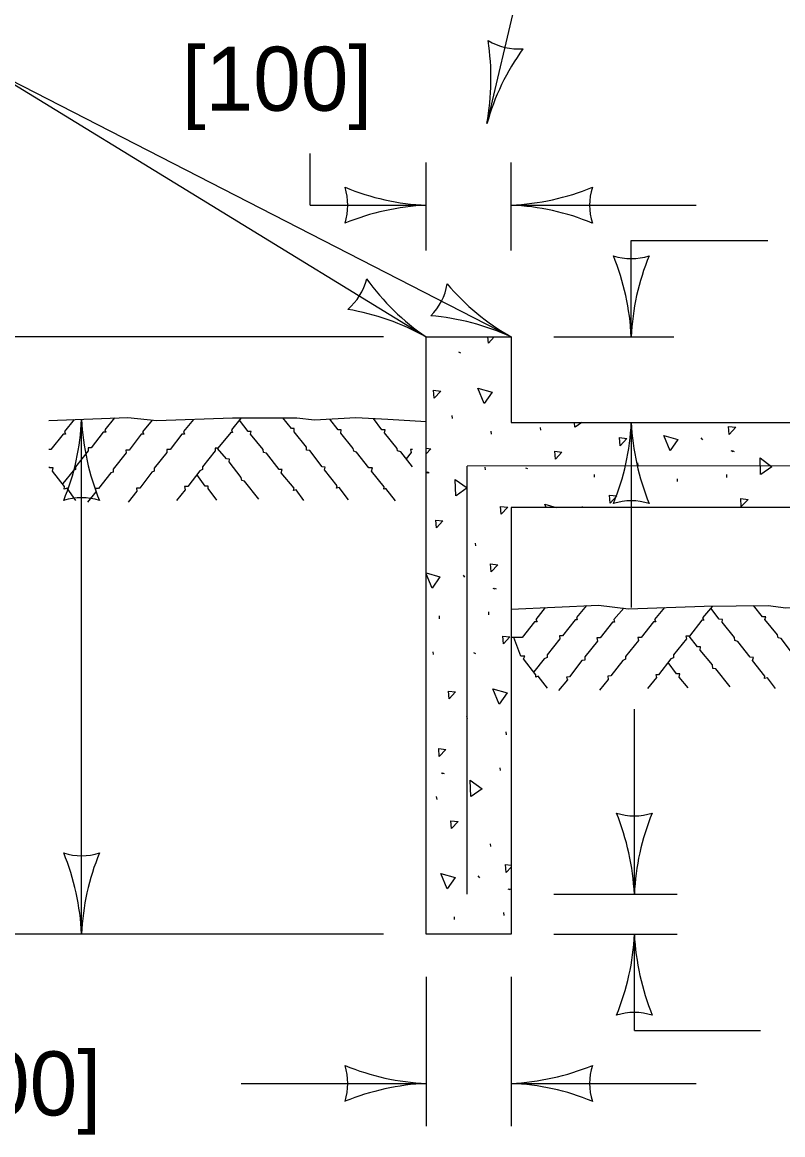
# Model space of a CAD drawing. Extents: x 49991.4 to 50021, y 49987.6 to 50011.4.
# Drawn here: x 50000.909 to 50001.622, y 49989.384 to 49990.427 of the extents above; entities that cross this region are included whole.
import ezdxf

# ---------------------------------------------------------------- set-up
doc = ezdxf.new("R2010")
doc.units = 0
for name, color, linetype in [('Level 1', 7, 'Continuous'), ('Level 2', 7, 'Continuous'), ('Level 3', 7, 'Continuous')]:
    doc.layers.add(name, color=color, linetype=linetype)

msp = doc.modelspace()

# ---------------------------------------------------------------- linework, layer by layer
at = {"layer": 'Level 1'}
for p, q in [((50001.2875, 49989.5723), (50001.2875, 49990.1317)), ((50001.2875, 49990.1317), (50001.3671, 49990.1317)), ((50001.3671, 49990.1317), (50001.3671, 49990.0516)), ((50001.3179, 49990.1177), (50001.3197, 49990.1169)), ((50001.3121, 49990.0554), (50001.3117, 49990.0581)), ((50001.3487, 49990.0406), (50001.3485, 49990.0433)), ((50001.3671, 49990.0516), (50002.1666, 49990.0516)), ((50001.395, 49990.0444), (50001.3947, 49990.047)), ((50001.5449, 49990.0371), (50001.5463, 49990.0352)), ((50001.5729, 49990.0252), (50001.5748, 49990.0243)), ((50001.5741, 49990.0252), (50001.576, 49990.0243)), ((50002.1646, 49990.0116), (50001.326, 49990.0107)), ((50001.4862, 49990.0111), (50001.4859, 49990.0137)), ((50001.2874, 49990.0052), (50001.2891, 49990.0043)), ((50001.2886, 49990.0052), (50001.2903, 49990.0043)), ((50001.326, 49989.6096), (50001.326, 49990.0107)), ((50001.3429, 49990.0072), (50001.3427, 49990.0098)), ((50001.3806, 49990.0091), (50001.3824, 49990.0083)), ((50001.4453, 49990.0003), (50001.4451, 49990.0028)), ((50001.5692, 49990), (50001.569, 49990.0027)), ((50001.523, 49989.9964), (50001.5228, 49989.9989)), ((50002.1852, 49989.972), (50001.3671, 49989.972)), ((50001.3671, 49989.972), (50001.3671, 49989.5723)), ((50001.4334, 49989.9727), (50001.4341, 49989.972)), ((50001.3339, 49989.9359), (50001.3336, 49989.9385)), ((50001.322, 49989.9085), (50001.3234, 49989.9066)), ((50001.35, 49989.8965), (50001.3519, 49989.8956)), ((50001.3514, 49989.8965), (50001.3531, 49989.8956)), ((50001.3001, 49989.8676), (50001.2999, 49989.8703)), ((50001.3463, 49989.8713), (50001.3461, 49989.8741)), ((50001.2943, 49989.8341), (50001.2941, 49989.8368)), ((50001.3319, 49989.836), (50001.3338, 49989.8351)), ((50001.3261, 49989.7738), (50001.3257, 49989.7764)), ((50001.3628, 49989.759), (50001.3625, 49989.7617)), ((50001.3014, 49989.7235), (50001.3031, 49989.7227)), ((50001.3026, 49989.7235), (50001.3043, 49989.7227)), ((50001.3571, 49989.7255), (50001.3568, 49989.7281)), ((50001.2977, 49989.6983), (50001.2972, 49989.7011)), ((50001.348, 49989.6542), (50001.3476, 49989.6568)), ((50001.336, 49989.6268), (50001.3375, 49989.6249)), ((50001.3641, 49989.6148), (50001.3659, 49989.614)), ((50001.3654, 49989.6148), (50001.3671, 49989.614)), ((50001.3141, 49989.5859), (50001.3139, 49989.5886)), ((50001.3604, 49989.5897), (50001.3601, 49989.5924)), ((50001.3671, 49989.5723), (50001.2875, 49989.5723))]:
    msp.add_line(p, q, dxfattribs=at)
for points in [[(50001.3459, 49990.1259), (50001.3453, 49990.1317)], [(50001.3512, 49990.1317), (50001.3459, 49990.1259)], [(50001.295, 49990.0743), (50001.2944, 49990.0817), (50001.3011, 49990.081), (50001.295, 49990.0743)], [(50001.3417, 49990.0693), (50001.3359, 49990.0837), (50001.3492, 49990.0799), (50001.3419, 49990.0695)], [(50000.9341, 49990.0533), (50001.008, 49990.0563), (50001.0352, 49990.0533), (50001.1061, 49990.0558), (50001.1662, 49990.0559), (50001.1828, 49990.0539), (50001.2216, 49990.0563), (50001.2516, 49990.0547), (50001.2875, 49990.0525)], [(50000.9578, 49990.0543), (50000.9486, 49990.0431), (50000.9496, 49990.0406), (50000.9473, 49990.0406), (50000.9358, 49990.0263), (50000.9341, 49990.0263)], [(50000.9954, 49990.0558), (50000.9865, 49990.0448), (50000.9875, 49990.0426), (50000.985, 49990.0426), (50000.9736, 49990.0277), (50000.9709, 49990.0277), (50000.9709, 49990.025), (50000.9591, 49990.01), (50000.9591, 49990.0074), (50000.9567, 49990.0062), (50000.9471, 49989.9943)], [(50001.0309, 49990.0538), (50001.0218, 49990.0429), (50001.0229, 49990.0405), (50001.0206, 49990.0405), (50001.0093, 49990.0257), (50001.006, 49990.0257), (50001.0063, 49990.0231), (50000.9942, 49990.0078), (50000.9942, 49990.0051), (50000.992, 49990.0043), (50000.9806, 49989.9897), (50000.9777, 49989.9896), (50000.978, 49989.9866), (50000.9702, 49989.9768)], [(50001.0694, 49990.0545), (50001.0601, 49990.0431), (50001.061, 49990.0406), (50001.0587, 49990.0406), (50001.0476, 49990.0263), (50001.0446, 49990.0263), (50001.0447, 49990.0233), (50001.0327, 49990.0088), (50001.0327, 49990.006), (50001.0305, 49990.0049), (50001.0192, 49989.99), (50001.0161, 49989.9899), (50001.0164, 49989.9872), (50001.0084, 49989.9769)], [(50001.1142, 49990.0558), (50001.1051, 49990.0447), (50001.1061, 49990.0423), (50001.1044, 49990.0423), (50001.0922, 49990.0276), (50001.0897, 49990.0276), (50001.0899, 49990.0249), (50001.0779, 49990.01), (50001.0779, 49990.0074), (50001.0754, 49990.0062), (50001.0642, 49989.9916), (50001.061, 49989.9915), (50001.0617, 49989.9884), (50001.0536, 49989.9785)], [(50001.1728, 49989.9785), (50001.1656, 49989.9884), (50001.1632, 49989.9878), (50001.1637, 49989.9899), (50001.1517, 49990.0044), (50001.1525, 49990.0075), (50001.1498, 49990.0076), (50001.1379, 49990.0228), (50001.1351, 49990.0233), (50001.1347, 49990.0263), (50001.1229, 49990.0405), (50001.1234, 49990.0431), (50001.1206, 49990.0431), (50001.1125, 49990.0537)], [(50001.2146, 49989.9792), (50001.206, 49989.9906), (50001.2035, 49989.99), (50001.2042, 49989.9922), (50001.1923, 49990.0073), (50001.193, 49990.0098), (50001.1902, 49990.01), (50001.1784, 49990.0252), (50001.1755, 49990.0257), (50001.1755, 49990.0285), (50001.1637, 49990.0429), (50001.1638, 49990.0459), (50001.1612, 49990.0459), (50001.1533, 49990.0559)], [(50001.2588, 49989.9783), (50001.2497, 49989.9897), (50001.2479, 49989.9891), (50001.2481, 49989.9913), (50001.2363, 49990.006), (50001.2371, 49990.0091), (50001.2339, 49990.0091), (50001.2222, 49990.0238), (50001.2197, 49990.0247), (50001.219, 49990.0273), (50001.2074, 49990.0417), (50001.2079, 49990.0447), (50001.2051, 49990.0447), (50001.1972, 49990.0548)], [(50001.2746, 49990.01), (50001.2636, 49990.0242), (50001.2606, 49990.0249), (50001.2604, 49990.0273), (50001.2484, 49990.0418), (50001.2491, 49990.0447), (50001.2461, 49990.0448), (50001.238, 49990.0554)], [(50001.4266, 49990.0471), (50001.4265, 49990.0516)], [(50001.4333, 49990.0516), (50001.4269, 49990.0472)], [(50001.5714, 49990.0404), (50001.5707, 49990.0478), (50001.5774, 49990.0471), (50001.5714, 49990.0404)], [(50001.4691, 49990.0298), (50001.4686, 49990.0374), (50001.4753, 49990.0365), (50001.4691, 49990.0298)], [(50001.5159, 49990.025), (50001.51, 49990.0393), (50001.5233, 49990.0356), (50001.516, 49990.0252)], [(50001.1308, 49989.9798), (50001.1173, 49989.9966), (50001.1149, 49989.9973), (50001.1142, 49990), (50001.1028, 49990.0148), (50001.1031, 49990.0171), (50001.1005, 49990.0175), (50001.0921, 49990.0273)], [(50001.2746, 49990.0263), (50001.2728, 49990.0263), (50001.2734, 49990.0233), (50001.2686, 49990.0176)], [(50001.2875, 49990.0276), (50001.2919, 49990.027), (50001.2875, 49990.0223)], [(50001.4086, 49990.0172), (50001.408, 49990.0246), (50001.4147, 49990.0237), (50001.4086, 49990.0172)], [(50001.6007, 49990.0028), (50001.6003, 49990.0183), (50001.6114, 49990.0101), (50001.6011, 49990.0029)], [(50000.9594, 49989.9786), (50000.9511, 49989.9899), (50000.9484, 49989.9891), (50000.9488, 49989.9916), (50000.9376, 49990.0061), (50000.9381, 49990.0091), (50000.9351, 49990.0091), (50000.9341, 49990.01)], [(50001.0914, 49989.9789), (50001.0833, 49989.9896), (50001.0834, 49989.9919), (50001.0804, 49989.9919), (50001.0726, 49990.0029)], [(50001.3152, 49989.9828), (50001.3146, 49989.9983), (50001.3258, 49989.9902), (50001.3155, 49989.983)], [(50001.4599, 49989.9761), (50001.4593, 49989.9834), (50001.466, 49989.9827), (50001.4599, 49989.9761)], [(50001.5827, 49989.9727), (50001.5822, 49989.9802), (50001.589, 49989.9795), (50001.5827, 49989.9727)], [(50001.3576, 49989.9656), (50001.3572, 49989.973), (50001.3639, 49989.9723), (50001.3576, 49989.9656)], [(50001.3999, 49989.972), (50001.3986, 49989.9751), (50001.4093, 49989.972)], [(50001.2971, 49989.9528), (50001.2966, 49989.9602), (50001.3032, 49989.9594), (50001.2971, 49989.9528)], [(50001.3485, 49989.9117), (50001.3478, 49989.9192), (50001.3546, 49989.9183), (50001.3485, 49989.9117)], [(50001.2875, 49989.9106), (50001.3004, 49989.907), (50001.2932, 49989.8965)], [(50001.2931, 49989.8963), (50001.2875, 49989.9098)], [(50001.3671, 49989.8767), (50001.449, 49989.8805), (50001.4769, 49989.8771), (50001.5478, 49989.8795), (50001.6077, 49989.8801), (50001.6243, 49989.8779), (50001.663, 49989.8805), (50001.6931, 49989.8785), (50001.7157, 49989.8771)], [(50001.3991, 49989.8782), (50001.3902, 49989.8671), (50001.3914, 49989.8647), (50001.3888, 49989.8647), (50001.3774, 49989.8501), (50001.3671, 49989.8501)], [(50001.4377, 49989.88), (50001.4282, 49989.8688), (50001.4288, 49989.8666), (50001.4269, 49989.8666), (50001.4153, 49989.8516), (50001.4124, 49989.8516), (50001.4128, 49989.849), (50001.4009, 49989.834), (50001.4009, 49989.8314), (50001.3979, 49989.8303), (50001.3884, 49989.8181)], [(50001.4725, 49989.8776), (50001.4632, 49989.8671), (50001.464, 49989.8645), (50001.4621, 49989.8645), (50001.4504, 49989.8499), (50001.4475, 49989.8499), (50001.448, 49989.8468), (50001.436, 49989.8321), (50001.436, 49989.829), (50001.4332, 49989.8285), (50001.4218, 49989.8134), (50001.4189, 49989.8131), (50001.42, 49989.8105), (50001.4115, 49989.8004)], [(50001.5106, 49989.8782), (50001.5014, 49989.8671), (50001.5025, 49989.8647), (50001.5004, 49989.8647), (50001.4889, 49989.8501), (50001.4859, 49989.8501), (50001.4863, 49989.8472), (50001.4741, 49989.8323), (50001.4741, 49989.8299), (50001.4717, 49989.8287), (50001.4605, 49989.8141), (50001.4576, 49989.814), (50001.458, 49989.8109), (50001.45, 49989.8009)], [(50001.5557, 49989.8796), (50001.5462, 49989.8684), (50001.5476, 49989.8663), (50001.5457, 49989.8663), (50001.534, 49989.8515), (50001.5307, 49989.8515), (50001.5313, 49989.849), (50001.5192, 49989.8338), (50001.5192, 49989.8312), (50001.5166, 49989.8302), (50001.5052, 49989.8151), (50001.5025, 49989.8151), (50001.5032, 49989.8126), (50001.4949, 49989.8023)], [(50001.6146, 49989.8023), (50001.6072, 49989.8123), (50001.6045, 49989.8118), (50001.6048, 49989.814), (50001.5933, 49989.8287), (50001.594, 49989.8314), (50001.5911, 49989.8318), (50001.5795, 49989.8465), (50001.5765, 49989.8472), (50001.5763, 49989.85), (50001.5648, 49989.8645), (50001.5651, 49989.8671), (50001.562, 49989.8673), (50001.5541, 49989.8777)], [(50001.6561, 49989.8032), (50001.6473, 49989.8147), (50001.645, 49989.8142), (50001.6456, 49989.8163), (50001.634, 49989.8312), (50001.6345, 49989.8337), (50001.6315, 49989.834), (50001.6199, 49989.8492), (50001.6172, 49989.8497), (50001.6167, 49989.8526), (50001.6048, 49989.8671), (50001.6056, 49989.8696), (50001.6025, 49989.8696), (50001.5941, 49989.88)], [(50001.3598, 49989.8442), (50001.3593, 49989.8515), (50001.366, 49989.8508), (50001.3598, 49989.8442)], [(50001.401, 49989.8027), (50001.3923, 49989.814), (50001.3902, 49989.813), (50001.3902, 49989.8151), (50001.3788, 49989.8301), (50001.3798, 49989.8326), (50001.3763, 49989.8327), (50001.3696, 49989.8501)], [(50001.5724, 49989.8039), (50001.5588, 49989.8208), (50001.556, 49989.8211), (50001.5556, 49989.8244), (50001.544, 49989.8384), (50001.5446, 49989.8414), (50001.5417, 49989.8414), (50001.5338, 49989.8514)], [(50001.533, 49989.803), (50001.5246, 49989.8131), (50001.525, 49989.8161), (50001.5221, 49989.8161), (50001.5141, 49989.8266)], [(50001.309, 49989.7926), (50001.3085, 49989.7999), (50001.3151, 49989.7993), (50001.309, 49989.7926)], [(50001.3558, 49989.7876), (50001.3499, 49989.802), (50001.3632, 49989.7983), (50001.356, 49989.7878)], [(50001.2997, 49989.7388), (50001.2992, 49989.7461), (50001.3059, 49989.7453), (50001.2997, 49989.7388)], [(50001.3293, 49989.7012), (50001.3286, 49989.7166), (50001.3399, 49989.7085), (50001.3295, 49989.7013)], [(50001.3112, 49989.6711), (50001.3107, 49989.6785), (50001.3173, 49989.6777), (50001.3112, 49989.6711)], [(50001.3625, 49989.63), (50001.3619, 49989.6375), (50001.3671, 49989.6369)], [(50001.3072, 49989.6146), (50001.3013, 49989.629), (50001.3145, 49989.6253), (50001.3073, 49989.6148)], [(50001.3671, 49989.6351), (50001.3625, 49989.63)]]:
    msp.add_lwpolyline(points, dxfattribs=at)
at = {"layer": 'Level 3'}
for p, q in [((50001.5198, 49991.0769), (50001.3444, 49990.3315)), ((50000.8736, 49990.3852), (50001.2875, 49990.1317)), ((50000.8736, 49990.3852), (50001.3671, 49990.1317)), ((50001.1787, 49990.2551), (50001.1787, 49990.3036)), ((50001.2875, 49990.2126), (50001.2875, 49990.2951)), ((50001.3671, 49990.2126), (50001.3671, 49990.2951)), ((50001.1787, 49990.2551), (50001.2875, 49990.2551)), ((50001.3671, 49990.2551), (50001.5405, 49990.2551)), ((50001.4796, 49990.1317), (50001.4796, 49990.2219)), ((50001.4796, 49990.2219), (50001.6074, 49990.2219)), ((50001.2475, 49990.1317), (50000.4644, 49990.1317)), ((50001.4071, 49990.1317), (50001.5196, 49990.1317)), ((50000.9647, 49989.5723), (50000.9647, 49990.0545)), ((50001.4796, 49990.0516), (50001.4796, 49989.8782)), ((50001.4825, 49989.6096), (50001.4825, 49989.783)), ((50001.4071, 49989.6096), (50001.5225, 49989.6096)), ((50001.2475, 49989.5723), (50000.4644, 49989.5723)), ((50001.4071, 49989.5723), (50001.5225, 49989.5723)), ((50001.4825, 49989.482), (50001.4825, 49989.5723)), ((50001.2875, 49989.5323), (50001.2875, 49989.3924)), ((50001.3671, 49989.5323), (50001.3671, 49989.3924)), ((50001.4825, 49989.482), (50001.6008, 49989.482)), ((50001.1141, 49989.4324), (50001.2875, 49989.4324)), ((50001.3671, 49989.4324), (50001.5405, 49989.4324))]:
    msp.add_line(p, q, dxfattribs=at)
for centre, radius, start, end in [((50001.1152, 49990.3736), 0.233, 349.5909, 8.8408), ((50001.3738, 49990.4563), 0.0548, 238.9024, 274.6248), ((50001.5585, 49990.2717), 0.2223, 144.2196, 164.4031), ((50001.2967, 49990.4772), 0.2223, 247.456, 267.6395), ((50001.1593, 49990.2551), 0.0548, 342.1388, 17.8612), ((50001.3556, 49990.4878), 0.233, 272.8273, 292.0772), ((50001.4953, 49990.2551), 0.0548, 162.1388, 197.8612), ((50001.299, 49990.0224), 0.233, 92.8273, 112.0772), ((50001.3579, 49990.033), 0.2223, 67.456, 87.6395), ((50001.4796, 49990.2599), 0.0548, 252.1388, 287.8612), ((50001.2469, 49990.1202), 0.233, 2.8273, 22.0772), ((50001.7017, 49990.1225), 0.2223, 157.456, 177.6395), ((50001.1786, 49990.1993), 0.0548, 310.3153, 346.0377), ((50001.4124, 49990.3156), 0.2223, 215.6325, 235.816), ((50001.2531, 49990.1903), 0.0548, 314.9455, 350.6679), ((50001.4768, 49990.3251), 0.2223, 220.2627, 240.4462), ((50001.1746, 49989.9279), 0.233, 61.0038, 80.2536), ((50001.271, 49989.9195), 0.233, 65.634, 84.8839), ((50000.7426, 49990.0637), 0.2223, 337.456, 357.6395), ((50001.1974, 49990.066), 0.233, 182.8273, 202.0772), ((50001.2575, 49990.0608), 0.2223, 337.456, 357.6395), ((50001.7123, 49990.0631), 0.233, 182.8273, 202.0772), ((50000.9647, 49989.9263), 0.0548, 72.1388, 107.8612), ((50001.4796, 49989.9234), 0.0548, 72.1388, 107.8612), ((50001.4825, 49989.7378), 0.0548, 252.1388, 287.8612), ((50001.2498, 49989.5981), 0.233, 2.8273, 22.0772), ((50001.7046, 49989.6004), 0.2223, 157.456, 177.6395), ((50000.9647, 49989.7005), 0.0548, 252.1388, 287.8612), ((50000.732, 49989.5608), 0.233, 2.8273, 22.0772), ((50001.1868, 49989.5631), 0.2223, 157.456, 177.6395), ((50001.2604, 49989.5815), 0.2223, 337.456, 357.6395), ((50001.7152, 49989.5838), 0.233, 182.8273, 202.0772), ((50001.4825, 49989.4441), 0.0548, 72.1388, 107.8612), ((50001.2967, 49989.6545), 0.2223, 247.456, 267.6395), ((50001.1593, 49989.4324), 0.0548, 342.1388, 17.8612), ((50001.3556, 49989.6651), 0.233, 272.8273, 292.0772), ((50001.4953, 49989.4324), 0.0548, 162.1388, 197.8612), ((50001.299, 49989.1997), 0.233, 92.8273, 112.0772), ((50001.3579, 49989.2103), 0.2223, 67.456, 87.6395)]:
    msp.add_arc(centre, radius, start, end, dxfattribs=at)

# ---------------------------------------------------------------- texts
at = {"layer": 'Level 2'}
for s, p in [('[100]', (50001.0585, 49990.3436)), ('4" [100]', (50000.7091, 49989.4024))]:
    msp.add_text(s, height=0.06, dxfattribs=at).set_placement(p)

doc.saveas('drawing.dxf')
